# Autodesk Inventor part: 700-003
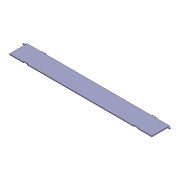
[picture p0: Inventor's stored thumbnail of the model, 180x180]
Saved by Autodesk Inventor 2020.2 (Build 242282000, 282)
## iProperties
Created: 2018-01
Part Number: 700-003
Material: Ogólne
Document SubType Name: Modeling
Designer: F.Stasiak
Density: 1 g/cm^3
Appearance: Szaroniebieska
Manager: www.cadconsulting.pl
Company: Fabian Stasiak CAD Consulting
Author: F.Stasiak
Subject: Zbiór ćwiczeń. Autodesk Inventor 2020. Kurs podstawowy
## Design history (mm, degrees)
sketch "Szkic1"
  geometry: L1 (2000, -250)-(-2000, -250); L2 (-2000, -250)-(-2000, 250); L3 (-2000, 250)-(2000, 250); L4 (2000, 250)-(2000, -250); L5 (2000, -250)-(-2000, 250); L6 (-2000, -250)-(2000, 250); 1 further point
  constraints: 12 end point, 2 midpoint, 2 parallel, 1 horizontal, 1 perpendicular
  dimensions: "d0" = 4000 distance of L2.end L3.end; "d1" = 500 distance of L1.end L2.end
extrude "Wyciągnięcie proste1" new body sketch "Szkic1" stored distance "d2" = 20; taper "d3" = 0 deg
sketch "Szkic2"
  geometry: L1 (-2000, -250)-(2000, -250) reference; L2 (-2000, 250)-(-2000, -250) reference; L3 (-1600, -250)-(-1600, -228); L4 (-1600, -228)-(-1500, -228); L5 (-1500, -228)-(-1500, -250); 1 further point
  constraints: 6 end point, 3 perpendicular, 2 point on line
  dimensions: "d4" = 22 distance of L3.start L3.end; "d5" = 100 distance of L3.end L4.end; "d6" = 400 distance between parallel lines of L2 L3
extrude "Wyciągnięcie proste2" cut sketch "Szkic2" extent not by distance; stored distance "d7" = 10; taper "d8" = 0 deg
sketch "Szkic3"
  geometry: L1 (20, 0)-(0, 0) reference; C1 r 5 at (10, 10); 2 further points
  constraints: 1 centre point, 1 midpoint, 1 vertical alignment
  dimensions: "d9" = 10 diameter of C1; "d10" = 10 distance from line of C1.centre L1
extrude "Wyciągnięcie proste3" join sketch "Szkic3" stored distance "d11" = 10; taper "d12" = 0 deg
sketch "Szkic4"
  geometry: L1 (2000, 250)-(-2000, 250) reference; L2 (-1600, -250)-(-1600, -228) reference; L3 (-1500, -228)-(-1500, -250) reference; L4 (-1600, 250)-(-1600, 268); L5 (-1600, 268)-(-1500, 268); L6 (-1500, 268)-(-1500, 250); 3 further points
  constraints: 6 end point, 2 collinear, 2 perpendicular, 2 point on line, 1 vertical
  dimensions: "d13" = 18 distance between parallel lines of L5 L1
extrude "Wyciągnięcie proste4" join sketch "Szkic4" distance "d14" = 20; taper "d15" = 0 deg
sketch "Szkic5"
  geometry: L1 (0, 18)-(20, 18) reference; C1 r 10 at (10, 18); 1 further point
  constraints: 1 centre point, 1 midpoint
  dimensions: "d16" = 20 diameter of C1
extrude "Wyciągnięcie proste5" join sketch "Szkic5" stored distance "d17" = 10; taper "d18" = 0 deg
sketch "Szkic6"
  geometry: C1 r 5.5 at (10, 18); A1 r 10 centre (10, 18) between (20, 18) and (0, 18) reference; 1 further point
  constraints: 1 centre point, 1 coincident
  dimensions: "d19" = 11 diameter of C1
extrude "Wyciągnięcie proste6" cut sketch "Szkic6" extent not by distance; stored distance "d20" = 10; taper "d21" = 0 deg
sketch "Szkic7"
  geometry: L1 (20, 0)-(0, 0) reference; C1 r 20 at (10, 450); 1 further point
  constraints: 1 centre point, 1 midpoint, 1 vertical alignment
  dimensions: "d22" = 40 diameter of C1; "d25" = 450 distance from line of L1 C1.centre
extrude "Wyciągnięcie proste7" join sketch "Szkic7" distance "d23" = 55; taper "d24" = 0 deg
mirror "Odbij1"
node "Bryła1"
